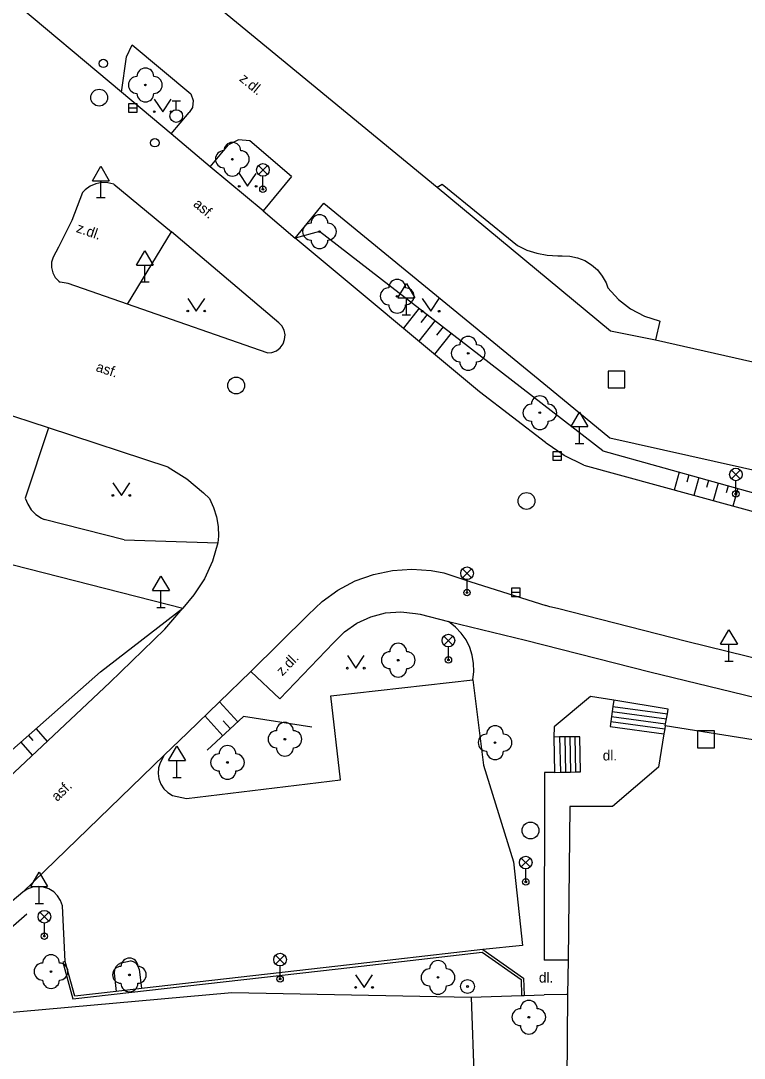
# Model space of a CAD drawing. Extents: x -642282 to -641982, y -1041678 to -1041427.
# Drawn here: x -642072.2 to -642029.3, y -1041642 to -1041580.5 of the extents above; entities that cross this region are included whole.
import ezdxf

# ---------------------------------------------------------------- set-up
doc = ezdxf.new("R2010")
doc.units = 0
for name, color, linetype in [('Budovy', 7, 'Continuous'), ('Budovy vstupy', 7, 'Continuous'), ('Ploty', 7, 'Continuous'), ('Pol_bod_pole', 7, 'Continuous'), ('Popis povrchů', 7, 'Continuous'), ('Rozhraní ploch 1', 7, 'Continuous'), ('Rozhraní ploch 2', 7, 'Continuous'), ('Ter_hr__hladina', 7, 'Continuous'), ('Vstup na pozemky', 7, 'Continuous'), ('Výšk_šrafy', 7, 'Continuous'), ('Zeleň - stromy', 7, 'Continuous'), ('Znaky doprava', 7, 'Continuous'), ('Znaky kanalizace', 7, 'Continuous'), ('Znaky voda', 7, 'Continuous'), ('Značky doprava', 7, 'Continuous'), ('Značky KM', 7, 'Continuous'), ('Šachty ner_', 7, 'Continuous')]:
    doc.layers.add(name, color=color, linetype=linetype)

msp = doc.modelspace()

# ---------------------------------------------------------------- linework, layer by layer
at = {"layer": 'Budovy'}
for p, q in [((-642062.51, -1041578.02), (-642047.49, -1041590.37)), ((-642047.49, -1041590.37), (-642047.2, -1041590.2)), ((-642047.49, -1041590.37), (-642037.23, -1041598.88)), ((-642047.2, -1041590.2), (-642042.75, -1041593.83)), ((-642042.75, -1041593.83), (-642042.185, -1041594.099)), ((-642042.185, -1041594.099), (-642041.591, -1041594.293)), ((-642041.591, -1041594.293), (-642040.976, -1041594.41)), ((-642040.976, -1041594.41), (-642040.352, -1041594.447)), ((-642040.352, -1041594.447), (-642040.1, -1041594.44)), ((-642040.1, -1041594.44), (-642039.637, -1041594.457)), ((-642039.637, -1041594.457), (-642039.183, -1041594.553)), ((-642039.183, -1041594.553), (-642038.752, -1041594.725)), ((-642038.752, -1041594.725), (-642038.358, -1041594.969)), ((-642038.358, -1041594.969), (-642038.011, -1041595.277)), ((-642038.011, -1041595.277), (-642037.722, -1041595.639)), ((-642037.722, -1041595.639), (-642037.499, -1041596.046)), ((-642037.499, -1041596.046), (-642037.39, -1041596.34)), ((-642037.39, -1041596.34), (-642036.769, -1041597.022)), ((-642036.769, -1041597.022), (-642036.039, -1041597.588)), ((-642036.039, -1041597.588), (-642035.223, -1041598.018)), ((-642035.223, -1041598.018), (-642034.344, -1041598.299)), ((-642034.31, -1041598.31), (-642034.57, -1041599.43)), ((-642034.344, -1041598.299), (-642034.31, -1041598.31)), ((-642037.23, -1041598.88), (-642034.57, -1041599.43)), ((-642034.57, -1041599.43), (-642028.19, -1041600.87)), ((-642033.99, -1041622.3), (-642034.019, -1041622.476)), ((-642004.78, -1041626.91), (-642033.99, -1041622.3)), ((-642034.067, -1041622.772), (-642034.39, -1041624.74)), ((-642034.019, -1041622.476), (-642034.067, -1041622.772)), ((-642034.39, -1041624.74), (-642037.12, -1041627.08)), ((-642039.65, -1041627.08), (-642039.75, -1041636.18)), ((-642037.12, -1041627.08), (-642039.65, -1041627.08)), ((-642039.75, -1041636.18), (-642039.771, -1041638.209)), ((-642039.771, -1041638.209), (-642039.85, -1041645.86))]:
    msp.add_line(p, q, dxfattribs=at)
at = {"layer": 'Budovy vstupy'}
msp.add_line((-642035.192, -1041625.428), (-642036.439, -1041626.496), dxfattribs=at)
at = {"layer": 'Ploty'}
for p, q in [((-642076.13, -1041639.56), (-642059.653, -1041638.102)), ((-642059.653, -1041638.102), (-642045.48, -1041638.38)), ((-642045.48, -1041638.38), (-642044.75, -1041659.01))]:
    msp.add_line(p, q, dxfattribs=at)
msp.add_lwpolyline([(-642045.48, -1041638.38), (-642042.496, -1041638.277), (-642042.354, -1041638.272), (-642041.153, -1041638.231)], dxfattribs=at)
at = {"layer": 'Pol_bod_pole'}
for radius in [0.412, 0.05]:
    msp.add_circle((-642045.7, -1041637.74), radius, dxfattribs=at)
at = {"layer": 'Rozhraní ploch 1'}
for p, q in [((-642066.2, -1041584.74), (-642075.74, -1041576.74)), ((-642065.9, -1041582.65), (-642065.56, -1041581.95)), ((-642065.56, -1041581.95), (-642062.09, -1041584.84)), ((-642066.2, -1041584.74), (-642065.9, -1041582.65)), ((-642063.256, -1041587.224), (-642066.2, -1041584.74)), ((-642062.09, -1041584.84), (-642061.946, -1041585.248)), ((-642061.946, -1041585.248), (-642061.997, -1041585.65)), ((-642063.256, -1041587.224), (-642062.19, -1041585.96)), ((-642061.997, -1041585.65), (-642062.19, -1041585.96)), ((-642060.948, -1041589.171), (-642059.85, -1041587.87)), ((-642059.262, -1041587.574), (-642059.85, -1041587.87)), ((-642058.6, -1041587.62), (-642059.262, -1041587.574)), ((-642056.13, -1041589.74), (-642058.6, -1041587.62)), ((-642056.13, -1041589.74), (-642057.81, -1041591.78)), ((-642066.65, -1041590.2), (-642063.24, -1041593.03)), ((-642055.9, -1041593.39), (-642054.21, -1041591.32)), ((-642054.21, -1041591.32), (-642040.74, -1041602.37)), ((-642057.81, -1041591.78), (-642055.9, -1041593.39)), ((-642065.84, -1041597.3), (-642063.24, -1041593.03)), ((-642056.87, -1041598.41), (-642063.24, -1041593.03)), ((-642044.99, -1041602.5), (-642055.9, -1041593.39)), ((-642069.36, -1041596.08), (-642069.83, -1041596.01)), ((-642065.84, -1041597.3), (-642069.36, -1041596.08)), ((-642057.57, -1041600.19), (-642065.84, -1041597.3)), ((-642041.09, -1041605.51), (-642044.99, -1041602.5)), ((-642040.74, -1041602.37), (-642037.27, -1041605.23)), ((-642070.523, -1041604.633), (-642074.797, -1041603.23)), ((-642070.523, -1041604.633), (-642071.89, -1041608.8)), ((-642063.43, -1041606.96), (-642070.523, -1041604.633)), ((-642037.27, -1041605.23), (-642021.07, -1041608.86)), ((-642038.82, -1041606.85), (-642012.91, -1041613.95)), ((-642083.78, -1041609.89), (-642062.57, -1041615.32)), ((-642066.04, -1041611.28), (-642070.77, -1041610.07)), ((-642066.04, -1041611.28), (-642060.48, -1041611.45)), ((-642047.11, -1041613.22), (-642045.5, -1041613.77)), ((-642045.5, -1041613.77), (-642041.06, -1041615.16)), ((-642063.62, -1041616.56), (-642062.57, -1041615.32)), ((-642040.82, -1041615.24), (-642041.06, -1041615.16)), ((-642040.38, -1041615.35), (-642040.82, -1041615.24)), ((-642032.73, -1041617.3), (-642040.38, -1041615.35)), ((-642058.53, -1041619.08), (-642055.14, -1041615.72)), ((-642066.88, -1041619.72), (-642063.62, -1041616.56)), ((-642056.81, -1041620.69), (-642053.63, -1041617.37)), ((-642042.26, -1041617.21), (-642034.9, -1041619.09)), ((-642018.73, -1041620.73), (-642032.73, -1041617.3)), ((-642062.29, -1041622.7), (-642058.53, -1041619.08)), ((-642056.81, -1041620.69), (-642058.53, -1041619.08)), ((-642034.9, -1041619.09), (-642010.36, -1041625.09)), ((-642076.72, -1041628.96), (-642066.88, -1041619.72)), ((-642062.29, -1041622.7), (-642063.66, -1041624.029)), ((-642063.66, -1041624.029), (-642072.03, -1041632.15)), ((-642041.14, -1041625.06), (-642041.16, -1041636.18)), ((-642039.75, -1041636.18), (-642041.16, -1041636.18))]:
    msp.add_line(p, q, dxfattribs=at)
for points in [[(-642057.81, -1041591.78), (-642060.948, -1041589.171), (-642063.256, -1041587.224)], [(-642066.65, -1041590.2), (-642067.003, -1041590.111), (-642067.367, -1041590.101), (-642067.724, -1041590.171), (-642068.057, -1041590.317), (-642068.351, -1041590.532), (-642068.51, -1041590.7)], [(-642068.51, -1041590.7), (-642069.14, -1041592.35), (-642069.917, -1041593.936), (-642070.25, -1041594.52)], [(-642070.25, -1041594.52), (-642070.334, -1041594.824), (-642070.339, -1041595.138), (-642070.265, -1041595.444), (-642070.116, -1041595.722), (-642069.903, -1041595.953), (-642069.83, -1041596.01)], [(-642057.57, -1041600.19), (-642057.288, -1041600.166), (-642057.024, -1041600.064), (-642056.798, -1041599.892), (-642056.629, -1041599.665), (-642056.531, -1041599.4), (-642056.509, -1041599.117), (-642056.568, -1041598.84), (-642056.701, -1041598.59), (-642056.87, -1041598.41)], [(-642038.82, -1041606.85), (-642039.97, -1041606.269), (-642041.038, -1041605.55), (-642041.09, -1041605.51)], [(-642063.43, -1041606.96), (-642062.333, -1041607.659), (-642061.329, -1041608.488), (-642060.99, -1041608.82)], [(-642071.89, -1041608.8), (-642071.749, -1041609.165), (-642071.536, -1041609.495), (-642071.262, -1041609.774), (-642070.936, -1041609.992), (-642070.77, -1041610.07)], [(-642060.99, -1041608.82), (-642060.74, -1041609.348), (-642060.564, -1041609.905), (-642060.467, -1041610.48), (-642060.448, -1041611.064), (-642060.48, -1041611.45)], [(-642060.48, -1041611.45), (-642060.809, -1041612.543), (-642061.287, -1041613.58), (-642061.906, -1041614.54), (-642062.57, -1041615.32)], [(-642055.14, -1041615.72), (-642054.31, -1041614.923), (-642053.377, -1041614.25), (-642052.36, -1041613.711), (-642051.279, -1041613.319), (-642050.153, -1041613.081), (-642049.005, -1041613.001), (-642047.857, -1041613.08), (-642047.11, -1041613.22)], [(-642053.63, -1041617.37), (-642052.991, -1041616.731), (-642052.25, -1041616.214), (-642051.429, -1041615.835), (-642050.555, -1041615.607), (-642049.654, -1041615.536), (-642048.79, -1041615.63), (-642048.5, -1041615.68)], [(-642048.5, -1041615.68), (-642046.83, -1041616.11), (-642042.26, -1041617.21)], [(-642045.385, -1041619.567), (-642045.326, -1041619.081), (-642045.338, -1041618.591), (-642045.421, -1041618.109), (-642045.573, -1041617.643), (-642045.791, -1041617.204), (-642046.071, -1041616.802), (-642046.405, -1041616.444), (-642046.83, -1041616.11)], [(-642033.99, -1041622.3), (-642033.968, -1041622.18), (-642033.915, -1041621.885), (-642033.862, -1041621.589), (-642033.81, -1041621.3), (-642037.043, -1041620.78), (-642038.41, -1041620.56), (-642040.57, -1041622.35)], [(-642040.57, -1041622.35), (-642040.591, -1041622.969), (-642040.55, -1041625.05), (-642041.14, -1041625.06)], [(-642072.03, -1041632.15), (-642073.821, -1041633.634), (-642075.756, -1041634.925), (-642077.813, -1041636.011), (-642079.86, -1041636.84)]]:
    msp.add_lwpolyline(points, dxfattribs=at)
at = {"layer": 'Rozhraní ploch 2'}
for p, q in [((-642053.801, -1041620.512), (-642045.385, -1041619.567)), ((-642045.385, -1041619.567), (-642044.757, -1041624.615)), ((-642053.229, -1041625.499), (-642053.801, -1041620.512)), ((-642037.174, -1041621.74), (-642033.968, -1041622.18)), ((-642037.133, -1041621.442), (-642033.915, -1041621.885)), ((-642037.093, -1041621.145), (-642033.862, -1041621.589)), ((-642037.215, -1041622.037), (-642034.019, -1041622.476)), ((-642040.244, -1041622.948), (-642040.203, -1041625.043)), ((-642039.944, -1041622.946), (-642039.903, -1041625.037)), ((-642039.644, -1041622.944), (-642039.603, -1041625.031)), ((-642039.344, -1041622.942), (-642039.303, -1041625.025)), ((-642044.757, -1041624.615), (-642042.981, -1041630.355)), ((-642062.347, -1041626.603), (-642053.229, -1041625.499)), ((-642063.166, -1041626.419), (-642062.347, -1041626.603)), ((-642069.523, -1041636.25), (-642069.694, -1041632.962)), ((-642044.79, -1041635.55), (-642053.388, -1041636.543)), ((-642053.371, -1041636.692), (-642044.83, -1041635.706)), ((-642068.96, -1041638.306), (-642069.523, -1041636.25)), ((-642066.213, -1041636.334), (-642065.656, -1041636.215)), ((-642069.071, -1041638.469), (-642053.371, -1041636.692)), ((-642066.638, -1041636.945), (-642066.515, -1041638.029)), ((-642065.141, -1041636.705), (-642065.01, -1041637.859)), ((-642053.388, -1041636.543), (-642065.01, -1041637.859)), ((-642039.771, -1041638.209), (-642039.846, -1041638.21))]:
    msp.add_line(p, q, dxfattribs=at)
for points in [[(-642037.043, -1041620.78), (-642037.093, -1041621.145), (-642037.133, -1041621.442), (-642037.174, -1041621.74), (-642037.215, -1041622.037), (-642037.256, -1041622.334), (-642034.067, -1041622.772)], [(-642040.55, -1041625.05), (-642040.203, -1041625.043), (-642039.903, -1041625.037), (-642039.603, -1041625.031), (-642039.303, -1041625.025), (-642039.003, -1041625.02), (-642039.044, -1041622.939), (-642039.344, -1041622.942), (-642039.644, -1041622.944), (-642039.944, -1041622.946), (-642040.244, -1041622.948), (-642040.591, -1041622.969)], [(-642063.66, -1041624.029), (-642063.909, -1041624.477), (-642064.002, -1041624.791), (-642064.025, -1041625.117), (-642063.977, -1041625.441), (-642063.86, -1041625.747), (-642063.68, -1041626.02), (-642063.445, -1041626.247), (-642063.166, -1041626.419)], [(-642042.981, -1041630.355), (-642042.436, -1041635.315), (-642044.79, -1041635.55)], [(-642069.694, -1041632.962), (-642069.8, -1041632.647), (-642069.975, -1041632.364), (-642070.21, -1041632.128), (-642070.492, -1041631.952), (-642070.807, -1041631.845), (-642071.137, -1041631.812), (-642071.467, -1041631.855), (-642071.778, -1041631.972), (-642072.03, -1041632.15)], [(-642044.83, -1041635.706), (-642042.529, -1041637.325), (-642042.496, -1041638.277)], [(-642044.79, -1041635.55), (-642042.389, -1041637.24), (-642042.354, -1041638.272)], [(-642069.523, -1041636.25), (-642069.668, -1041636.29), (-642069.071, -1041638.469)], [(-642066.213, -1041636.334), (-642066.387, -1041636.428), (-642066.524, -1041636.571), (-642066.61, -1041636.749), (-642066.638, -1041636.945)], [(-642065.141, -1041636.705), (-642065.204, -1041636.527), (-642065.31, -1041636.386), (-642065.475, -1041636.269), (-642065.656, -1041636.215)], [(-642065.01, -1041637.859), (-642066.515, -1041638.029), (-642068.96, -1041638.306)]]:
    msp.add_lwpolyline(points, dxfattribs=at)
at = {"layer": 'Ter_hr__hladina'}
for p, q in [((-642054.47, -1041593.01), (-642055.9, -1041593.39)), ((-642037.68, -1041606), (-642054.47, -1041593.01)), ((-642037.68, -1041606), (-642023.75, -1041609.9)), ((-642067.43, -1041619.1), (-642062.57, -1041615.32)), ((-642077.54, -1041628.01), (-642067.43, -1041619.1)), ((-642061.114, -1041623.728), (-642058.96, -1041621.75)), ((-642054.93, -1041622.38), (-642058.96, -1041621.75)), ((-642076.35, -1041637.37), (-642071.797, -1041633.436))]:
    msp.add_line(p, q, dxfattribs=at)
at = {"layer": 'Vstup na pozemky'}
msp.add_line((-642039.846, -1041638.21), (-642041.153, -1041638.231), dxfattribs=at)
at = {"layer": 'Výšk_šrafy'}
for p, q in [((-642048.574, -1041597.546), (-642049.498, -1041598.736)), ((-642047.626, -1041598.282), (-642048.576, -1041599.506)), ((-642048.1, -1041597.914), (-642048.475, -1041598.397)), ((-642047.152, -1041598.65), (-642047.537, -1041599.146)), ((-642046.678, -1041599.018), (-642047.654, -1041600.276)), ((-642033.163, -1041607.265), (-642033.461, -1041608.328)), ((-642032.585, -1041607.426), (-642032.704, -1041607.85)), ((-642032.007, -1041607.588), (-642032.303, -1041608.645)), ((-642031.429, -1041607.75), (-642031.547, -1041608.171)), ((-642030.852, -1041607.912), (-642031.146, -1041608.961)), ((-642030.274, -1041608.074), (-642030.391, -1041608.492)), ((-642029.696, -1041608.235), (-642029.988, -1041609.278)), ((-642059.304, -1041622.065), (-642060.396, -1041620.876)), ((-642060.188, -1041622.877), (-642061.261, -1041621.709)), ((-642059.746, -1041622.471), (-642060.179, -1041622)), ((-642071.706, -1041622.868), (-642071.439, -1041623.171)), ((-642071.256, -1041622.472), (-642070.602, -1041623.215)), ((-642072.156, -1041623.265), (-642071.476, -1041624.036))]:
    msp.add_line(p, q, dxfattribs=at)
at = {"layer": 'Zeleň - stromy'}
for centre in [(-642064.78, -1041584.32), (-642059.63, -1041588.72), (-642054.47, -1041593.01), (-642049.87, -1041596.84), (-642045.66, -1041600.22), (-642041.42, -1041603.74), (-642049.805, -1041618.404), (-642056.515, -1041623.088), (-642044.07, -1041623.29), (-642059.917, -1041624.461), (-642070.368, -1041636.856), (-642065.724, -1041637.052), (-642047.448, -1041637.2), (-642042.07, -1041639.56)]:
    msp.add_circle(centre, 0.05, dxfattribs=at)
for centre, start, end in [((-642064.78, -1041583.82), 0, 180), ((-642065.28, -1041584.32), 90, 270), ((-642064.28, -1041584.32), 270, 90), ((-642064.78, -1041584.82), 180, 0), ((-642059.63, -1041588.22), 0, 180), ((-642060.13, -1041588.72), 90, 270), ((-642059.13, -1041588.72), 270, 90), ((-642059.63, -1041589.22), 180, 0), ((-642054.47, -1041592.51), 0, 180), ((-642054.97, -1041593.01), 90, 270), ((-642053.97, -1041593.01), 270, 90), ((-642054.47, -1041593.51), 180, 0), ((-642049.87, -1041596.34), 0, 180), ((-642050.37, -1041596.84), 90, 270), ((-642049.37, -1041596.84), 270, 90), ((-642049.87, -1041597.34), 180, 0), ((-642045.66, -1041599.72), 0, 180), ((-642046.16, -1041600.22), 90, 270), ((-642045.16, -1041600.22), 270, 90), ((-642045.66, -1041600.72), 180, 0), ((-642041.92, -1041603.74), 90, 270), ((-642041.42, -1041603.24), 0, 180), ((-642040.92, -1041603.74), 270, 90), ((-642041.42, -1041604.24), 180, 0), ((-642049.805, -1041617.904), 0, 180), ((-642050.305, -1041618.404), 90, 270), ((-642049.305, -1041618.404), 270, 90), ((-642049.805, -1041618.904), 180, 0), ((-642056.515, -1041622.588), 0, 180), ((-642044.07, -1041622.79), 0, 180), ((-642057.015, -1041623.088), 90, 270), ((-642056.015, -1041623.088), 270, 90), ((-642044.57, -1041623.29), 90, 270), ((-642043.57, -1041623.29), 270, 90), ((-642059.917, -1041623.961), 0, 180), ((-642056.515, -1041623.588), 180, 0), ((-642060.417, -1041624.461), 90, 270), ((-642059.417, -1041624.461), 270, 90), ((-642044.07, -1041623.79), 180, 0), ((-642059.917, -1041624.961), 180, 0), ((-642070.368, -1041636.356), 0, 180), ((-642070.868, -1041636.856), 90, 270), ((-642069.868, -1041636.856), 270, 90), ((-642065.724, -1041636.552), 0, 180), ((-642047.448, -1041636.7), 0, 180), ((-642066.224, -1041637.052), 90, 270), ((-642065.224, -1041637.052), 270, 90), ((-642047.948, -1041637.2), 90, 270), ((-642046.948, -1041637.2), 270, 90), ((-642070.368, -1041637.356), 180, 0), ((-642065.724, -1041637.552), 180, 0), ((-642047.448, -1041637.7), 180, 0), ((-642042.07, -1041639.06), 0, 180), ((-642042.57, -1041639.56), 90, 270), ((-642041.57, -1041639.56), 270, 90), ((-642042.07, -1041640.06), 180, 0)]:
    msp.add_arc(centre, 0.5, start, end, dxfattribs=at)
at = {"layer": 'Znaky doprava'}
for p, q in [((-642058.085, -1041589.085), (-642057.555, -1041589.615)), ((-642058.085, -1041589.615), (-642057.555, -1041589.085)), ((-642057.82, -1041590.5), (-642057.82, -1041589.725)), ((-642030.075, -1041607.135), (-642029.545, -1041607.665)), ((-642030.075, -1041607.665), (-642029.545, -1041607.135)), ((-642029.81, -1041608.55), (-642029.81, -1041607.775)), ((-642045.995, -1041612.985), (-642045.465, -1041613.515)), ((-642045.995, -1041613.515), (-642045.465, -1041612.985)), ((-642045.73, -1041614.4), (-642045.73, -1041613.625)), ((-642047.096, -1041616.974), (-642046.566, -1041617.504)), ((-642047.096, -1041617.504), (-642046.566, -1041616.974)), ((-642046.831, -1041618.389), (-642046.831, -1041617.614)), ((-642042.516, -1041630.128), (-642041.986, -1041630.658)), ((-642042.516, -1041630.658), (-642041.986, -1041630.128)), ((-642042.251, -1041631.543), (-642042.251, -1041630.768)), ((-642071.028, -1041633.341), (-642070.498, -1041633.871)), ((-642071.028, -1041633.871), (-642070.498, -1041633.341)), ((-642070.763, -1041634.756), (-642070.763, -1041633.981)), ((-642057.066, -1041635.881), (-642056.536, -1041636.411)), ((-642057.066, -1041636.411), (-642056.536, -1041635.881)), ((-642056.801, -1041637.296), (-642056.801, -1041636.521))]:
    msp.add_line(p, q, dxfattribs=at)
for centre, radius in [((-642057.82, -1041589.35), 0.375), ((-642057.82, -1041590.5), 0.19), ((-642057.82, -1041590.5), 0.05), ((-642029.81, -1041607.4), 0.375), ((-642029.81, -1041608.55), 0.19), ((-642029.81, -1041608.55), 0.05), ((-642045.73, -1041613.25), 0.375), ((-642045.73, -1041614.4), 0.19), ((-642045.73, -1041614.4), 0.05), ((-642046.831, -1041617.239), 0.375), ((-642046.831, -1041618.389), 0.19), ((-642046.831, -1041618.389), 0.05), ((-642042.251, -1041630.393), 0.375), ((-642042.251, -1041631.543), 0.19), ((-642042.251, -1041631.543), 0.05), ((-642070.763, -1041633.606), 0.375), ((-642070.763, -1041634.756), 0.19), ((-642070.763, -1041634.756), 0.05), ((-642056.801, -1041636.146), 0.375), ((-642056.801, -1041637.296), 0.19), ((-642056.801, -1041637.296), 0.05)]:
    msp.add_circle(centre, radius, dxfattribs=at)
at = {"layer": 'Znaky kanalizace'}
for p, q in [((-642065.77, -1041585.68), (-642065.27, -1041585.68)), ((-642040.64, -1041606.31), (-642040.14, -1041606.31)), ((-642043.09, -1041614.38), (-642042.59, -1041614.38))]:
    msp.add_line(p, q, dxfattribs=at)
for points in [[(-642065.77, -1041585.93), (-642065.27, -1041585.93), (-642065.27, -1041585.43), (-642065.77, -1041585.43)], [(-642040.64, -1041606.56), (-642040.14, -1041606.56), (-642040.14, -1041606.06), (-642040.64, -1041606.06)], [(-642043.09, -1041614.63), (-642042.59, -1041614.63), (-642042.59, -1041614.13), (-642043.09, -1041614.13)]]:
    msp.add_lwpolyline(points, close=True, dxfattribs=at)
for centre in [(-642067.52, -1041585.07), (-642059.4, -1041602.13), (-642042.21, -1041608.97), (-642041.973, -1041628.496)]:
    msp.add_circle(centre, 0.5, dxfattribs=at)
at = {"layer": 'Znaky voda'}
for p, q in [((-642063.2, -1041585.26), (-642062.7, -1041585.26)), ((-642062.95, -1041585.785), (-642062.95, -1041585.26))]:
    msp.add_line(p, q, dxfattribs=at)
for centre, radius in [((-642067.27, -1041583.04), 0.25), ((-642062.95, -1041586.16), 0.375), ((-642064.22, -1041587.74), 0.25)]:
    msp.add_circle(centre, radius, dxfattribs=at)
at = {"layer": 'Značky doprava'}
for p, q in [((-642067.92, -1041589.99), (-642067.42, -1041589.14)), ((-642067.42, -1041589.14), (-642066.92, -1041589.99)), ((-642067.92, -1041589.99), (-642066.92, -1041589.99)), ((-642067.42, -1041590.99), (-642067.42, -1041589.99)), ((-642067.67, -1041590.99), (-642067.17, -1041590.99)), ((-642065.31, -1041594.99), (-642064.81, -1041594.14)), ((-642064.81, -1041594.14), (-642064.31, -1041594.99)), ((-642065.31, -1041594.99), (-642064.31, -1041594.99)), ((-642064.81, -1041595.99), (-642064.81, -1041594.99)), ((-642065.06, -1041595.99), (-642064.56, -1041595.99)), ((-642049.82, -1041596.93), (-642049.32, -1041596.08)), ((-642049.32, -1041596.08), (-642048.82, -1041596.93)), ((-642049.82, -1041596.93), (-642048.82, -1041596.93)), ((-642049.32, -1041597.93), (-642049.32, -1041596.93)), ((-642049.57, -1041597.93), (-642049.07, -1041597.93)), ((-642039.57, -1041604.56), (-642039.07, -1041603.71)), ((-642039.07, -1041603.71), (-642038.57, -1041604.56)), ((-642039.57, -1041604.56), (-642038.57, -1041604.56)), ((-642039.07, -1041605.56), (-642039.07, -1041604.56)), ((-642039.32, -1041605.56), (-642038.82, -1041605.56)), ((-642064.36, -1041614.28), (-642063.86, -1041613.43)), ((-642063.86, -1041613.43), (-642063.36, -1041614.28)), ((-642064.36, -1041614.28), (-642063.36, -1041614.28)), ((-642063.86, -1041615.28), (-642063.86, -1041614.28)), ((-642064.11, -1041615.28), (-642063.61, -1041615.28)), ((-642030.716, -1041617.46), (-642030.216, -1041616.61)), ((-642030.216, -1041616.61), (-642029.716, -1041617.46)), ((-642030.716, -1041617.46), (-642029.716, -1041617.46)), ((-642030.216, -1041618.46), (-642030.216, -1041617.46)), ((-642030.465, -1041618.46), (-642029.967, -1041618.46)), ((-642063.41, -1041624.348), (-642062.91, -1041623.498)), ((-642062.91, -1041623.498), (-642062.41, -1041624.348)), ((-642063.41, -1041624.348), (-642062.41, -1041624.348)), ((-642062.91, -1041625.348), (-642062.91, -1041624.348)), ((-642063.159, -1041625.348), (-642062.661, -1041625.348)), ((-642071.567, -1041631.814), (-642071.067, -1041630.964)), ((-642071.067, -1041630.964), (-642070.567, -1041631.814)), ((-642071.567, -1041631.814), (-642070.567, -1041631.814)), ((-642071.067, -1041632.814), (-642071.067, -1041631.814)), ((-642071.316, -1041632.814), (-642070.818, -1041632.814))]:
    msp.add_line(p, q, dxfattribs=at)
at = {"layer": 'Značky KM'}
for p, q in [((-642064.253, -1041585.152), (-642063.753, -1041585.902)), ((-642063.753, -1041585.902), (-642063.253, -1041585.152)), ((-642059.223, -1041589.572), (-642058.723, -1041590.322)), ((-642058.723, -1041590.322), (-642058.223, -1041589.572)), ((-642062.267, -1041596.963), (-642061.767, -1041597.713)), ((-642061.767, -1041597.713), (-642061.267, -1041596.963)), ((-642048.382, -1041596.978), (-642047.882, -1041597.728)), ((-642047.882, -1041597.728), (-642047.382, -1041596.978)), ((-642066.702, -1041607.89), (-642066.202, -1041608.64)), ((-642066.202, -1041608.64), (-642065.702, -1041607.89)), ((-642052.818, -1041618.127), (-642052.318, -1041618.877)), ((-642052.318, -1041618.877), (-642051.818, -1041618.127)), ((-642052.328, -1041637.045), (-642051.828, -1041637.795)), ((-642051.828, -1041637.795), (-642051.328, -1041637.045))]:
    msp.add_line(p, q, dxfattribs=at)
for centre in [(-642064.253, -1041585.902), (-642063.253, -1041585.902), (-642059.223, -1041590.322), (-642058.223, -1041590.322), (-642062.267, -1041597.713), (-642061.267, -1041597.713), (-642048.382, -1041597.728), (-642047.382, -1041597.728), (-642066.702, -1041608.64), (-642065.702, -1041608.64), (-642052.818, -1041618.877), (-642051.818, -1041618.877), (-642052.328, -1041637.795), (-642051.328, -1041637.795)]:
    msp.add_circle(centre, 0.05, dxfattribs=at)
at = {"layer": 'Šachty ner_'}
for points in [[(-642037.38, -1041602.27), (-642036.38, -1041602.27), (-642036.38, -1041601.27), (-642037.38, -1041601.27)], [(-642032.08, -1041623.6), (-642031.08, -1041623.6), (-642031.08, -1041622.6), (-642032.08, -1041622.6)]]:
    msp.add_lwpolyline(points, close=True, dxfattribs=at)

# ---------------------------------------------------------------- texts
at = {"layer": 'Popis povrchů'}
for s, rotation, p in [('z.dl.', 320.63655, (-642059.257, -1041584.033)), ('asf.', 319.8161, (-642061.988, -1041591.45)), ('z.dl.', 340.88415, (-642068.918, -1041593.024)), ('asf.', 341.83689, (-642067.753, -1041601.264)), ('z.dl.', 46.23387, (-642056.665, -1041619.375)), ('asf.', 44.13421, (-642070.003, -1041626.811))]:
    msp.add_text(s, height=0.6, rotation=rotation, dxfattribs=at).set_placement(p)
for p in [(-642037.692, -1041624.347), (-642041.473, -1041637.507)]:
    msp.add_text('dl.', height=0.6, dxfattribs=at).set_placement(p)

doc.saveas('drawing.dxf')
